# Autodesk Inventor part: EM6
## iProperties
IsCustomPart: 0
Created: 2006-02
Part Number: EM6
Material: Steel, Mild
Description: 六角ナット
Document SubType Name: Modeling
Standard: JIS B 1181
Designer: t-ikumi
Standards Organization: JIS
Language: ja-JP
Size Designation: 等級 3 仕上程度 並 M6
Categories: <MemberInstance><Categories><Category DisplayName="締結器具" InternalName="e4da775c-781d-43d5-af7c-5136215cf5a6" Mnemonic="FSTN"><Category DisplayName="ナット" Interna
Density: 1 g/cm^3
Author: t-ikumi
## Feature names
1. ボディ [Extrusion]
2. 面取り1 [Revolution]
3. ねじ [Hole]
4. 面取り2 [Chamfer]
5. 面取り3 [Chamfer]
